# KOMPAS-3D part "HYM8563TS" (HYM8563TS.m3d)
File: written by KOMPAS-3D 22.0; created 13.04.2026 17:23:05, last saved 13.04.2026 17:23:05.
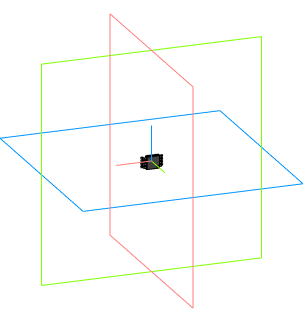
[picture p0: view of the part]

Document properties: Автор: Andrey; Полное имя файла: C:\Users\User1\Documents\HYM8563TS.m3d

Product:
- Part/product: HYM8563TS

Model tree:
1. Операция без истории:1
2. Операция без истории:2
3. Операция без истории:3
4. Операция без истории:4
5. Операция без истории:5
6. Операция без истории:6
7. Операция без истории:7
8. Операция без истории:8
9. Операция без истории:9
10. Операция без истории:10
